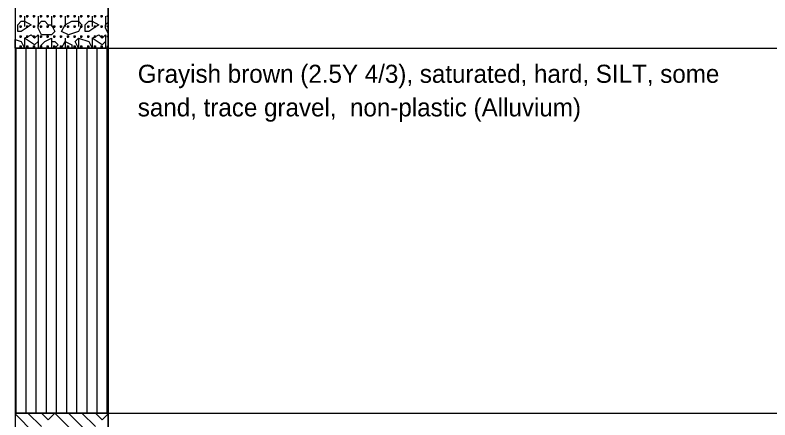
# Model space of a CAD drawing. Extents: x 9419 to 9552, y 6780 to 6865.
# Drawn here: x 9438.31 to 9447.62, y 6822.43 to 6827.42 of the extents above; entities that cross this region are included whole.
import ezdxf

# ---------------------------------------------------------------- set-up
doc = ezdxf.new("R2010")
doc.units = 0
doc.layers.add('7', color=7, linetype='Continuous')
doc.layers.add('8', color=7, linetype='Continuous')

msp = doc.modelspace()

# ---------------------------------------------------------------- linework, layer by layer
at = {"layer": '7'}
for p, q in [((9438.3144, 6832.0106), (9438.3144, 6827.0106)), ((9438.3144, 6832.0106), (9438.3144, 6827.0106)), ((9438.3144, 6832.0106), (9438.3144, 6827.0106)), ((9439.4627, 6827.0106), (9439.4627, 6832.0106)), ((9439.4627, 6827.0106), (9439.4627, 6832.0106)), ((9439.4627, 6827.0106), (9439.4627, 6832.0106)), ((9438.3144, 6827.0106), (9439.4627, 6827.0106)), ((9438.3144, 6827.0106), (9439.4627, 6827.0106)), ((9438.3144, 6827.0106), (9439.4627, 6827.0106)), ((9438.3144, 6827.0106), (9438.3144, 6822.5106)), ((9439.4627, 6827.0106), (9438.3144, 6827.0106)), ((9439.4627, 6822.5106), (9439.4627, 6827.0106)), ((9439.4627, 6827.0106), (9450.4053, 6827.0106)), ((9438.3144, 6822.5106), (9439.4627, 6822.5106)), ((9438.3144, 6822.5106), (9438.3144, 6822.0107)), ((9439.4627, 6822.5106), (9438.3144, 6822.5106)), ((9439.4627, 6822.0107), (9439.4627, 6822.5106)), ((9439.4627, 6822.5106), (9450.4053, 6822.5106))]:
    msp.add_line(p, q, dxfattribs=at)
for points in [[(9438.3144, 6850.5283), (9438.3144, 6821.9829)], [(9439.4627, 6850.5283), (9439.4627, 6821.9829)]]:
    msp.add_lwpolyline(points, dxfattribs=at)
at = {"layer": '8'}
for p, q in [((9438.4303, 6827.4065), (9438.4303, 6827.2815)), ((9438.5969, 6827.4065), (9438.5969, 6827.2815)), ((9438.7636, 6827.4065), (9438.7636, 6827.2815)), ((9438.9303, 6827.4065), (9438.9303, 6827.2815)), ((9439.0969, 6827.4065), (9439.0969, 6827.2815)), ((9439.2636, 6827.4065), (9439.2636, 6827.2815)), ((9439.4303, 6827.4065), (9439.4303, 6827.2815)), ((9438.4303, 6827.1356), (9438.4303, 6827.0106)), ((9438.5969, 6827.1356), (9438.5969, 6827.0106)), ((9438.7636, 6827.1356), (9438.7636, 6827.0106)), ((9438.9303, 6827.1356), (9438.9303, 6827.0106)), ((9439.0969, 6827.1356), (9439.0969, 6827.0106)), ((9439.2636, 6827.1356), (9439.2636, 6827.0106)), ((9439.4303, 6827.1356), (9439.4303, 6827.0106)), ((9438.3261, 6826.7606), (9438.3261, 6827.0106)), ((9438.4511, 6826.7606), (9438.4511, 6827.0106)), ((9438.5761, 6826.7606), (9438.5761, 6827.0106)), ((9438.7011, 6826.7606), (9438.7011, 6827.0106)), ((9438.8261, 6826.7606), (9438.8261, 6827.0106)), ((9438.9511, 6826.7606), (9438.9511, 6827.0106)), ((9439.0761, 6826.7606), (9439.0761, 6827.0106)), ((9439.2011, 6826.7606), (9439.2011, 6827.0106)), ((9439.3261, 6826.7606), (9439.3261, 6827.0106)), ((9439.4511, 6826.7606), (9439.4511, 6827.0106)), ((9438.3261, 6826.5106), (9438.3261, 6826.7606)), ((9438.4511, 6826.5106), (9438.4511, 6826.7606)), ((9438.5761, 6826.5106), (9438.5761, 6826.7606)), ((9438.7011, 6826.5106), (9438.7011, 6826.7606)), ((9438.8261, 6826.5106), (9438.8261, 6826.7606)), ((9438.9511, 6826.5106), (9438.9511, 6826.7606)), ((9439.0761, 6826.5106), (9439.0761, 6826.7606)), ((9439.2011, 6826.5106), (9439.2011, 6826.7606)), ((9439.3261, 6826.5106), (9439.3261, 6826.7606)), ((9439.4511, 6826.5106), (9439.4511, 6826.7606)), ((9438.3261, 6826.2606), (9438.3261, 6826.5106)), ((9438.4511, 6826.2606), (9438.4511, 6826.5106)), ((9438.5761, 6826.2606), (9438.5761, 6826.5106)), ((9438.7011, 6826.2606), (9438.7011, 6826.5106)), ((9438.8261, 6826.2606), (9438.8261, 6826.5106)), ((9438.9511, 6826.2606), (9438.9511, 6826.5106)), ((9439.0761, 6826.2606), (9439.0761, 6826.5106)), ((9439.2011, 6826.2606), (9439.2011, 6826.5106)), ((9439.3261, 6826.2606), (9439.3261, 6826.5106)), ((9439.4511, 6826.2606), (9439.4511, 6826.5106)), ((9438.3261, 6826.0106), (9438.3261, 6826.2606)), ((9438.4511, 6826.0106), (9438.4511, 6826.2606)), ((9438.5761, 6826.0106), (9438.5761, 6826.2606)), ((9438.7011, 6826.0106), (9438.7011, 6826.2606)), ((9438.8261, 6826.0106), (9438.8261, 6826.2606)), ((9438.9511, 6826.0106), (9438.9511, 6826.2606)), ((9439.0761, 6826.0106), (9439.0761, 6826.2606)), ((9439.2011, 6826.0106), (9439.2011, 6826.2606)), ((9439.3261, 6826.0106), (9439.3261, 6826.2606)), ((9439.4511, 6826.0106), (9439.4511, 6826.2606)), ((9438.3261, 6825.7606), (9438.3261, 6826.0106)), ((9438.4511, 6825.7606), (9438.4511, 6826.0106)), ((9438.5761, 6825.7606), (9438.5761, 6826.0106)), ((9438.7011, 6825.7606), (9438.7011, 6826.0106)), ((9438.8261, 6825.7606), (9438.8261, 6826.0106)), ((9438.9511, 6825.7606), (9438.9511, 6826.0106)), ((9439.0761, 6825.7606), (9439.0761, 6826.0106)), ((9439.2011, 6825.7606), (9439.2011, 6826.0106)), ((9439.3261, 6825.7606), (9439.3261, 6826.0106)), ((9439.4511, 6825.7606), (9439.4511, 6826.0106)), ((9438.3261, 6825.5106), (9438.3261, 6825.7606)), ((9438.4511, 6825.5106), (9438.4511, 6825.7606)), ((9438.5761, 6825.5106), (9438.5761, 6825.7606)), ((9438.7011, 6825.5106), (9438.7011, 6825.7606)), ((9438.8261, 6825.5106), (9438.8261, 6825.7606)), ((9438.9511, 6825.5106), (9438.9511, 6825.7606)), ((9439.0761, 6825.5106), (9439.0761, 6825.7606)), ((9439.2011, 6825.5106), (9439.2011, 6825.7606)), ((9439.3261, 6825.5106), (9439.3261, 6825.7606)), ((9439.4511, 6825.5106), (9439.4511, 6825.7606)), ((9438.3261, 6825.2606), (9438.3261, 6825.5106)), ((9438.4511, 6825.2606), (9438.4511, 6825.5106)), ((9438.5761, 6825.2606), (9438.5761, 6825.5106)), ((9438.7011, 6825.2606), (9438.7011, 6825.5106)), ((9438.8261, 6825.2606), (9438.8261, 6825.5106)), ((9438.9511, 6825.2606), (9438.9511, 6825.5106)), ((9439.0761, 6825.2606), (9439.0761, 6825.5106)), ((9439.2011, 6825.2606), (9439.2011, 6825.5106)), ((9439.3261, 6825.2606), (9439.3261, 6825.5106)), ((9439.4511, 6825.2606), (9439.4511, 6825.5106)), ((9438.3261, 6825.0106), (9438.3261, 6825.2606)), ((9438.4511, 6825.0106), (9438.4511, 6825.2606)), ((9438.5761, 6825.0106), (9438.5761, 6825.2606)), ((9438.7011, 6825.0106), (9438.7011, 6825.2606)), ((9438.8261, 6825.0106), (9438.8261, 6825.2606)), ((9438.9511, 6825.0106), (9438.9511, 6825.2606)), ((9439.0761, 6825.0106), (9439.0761, 6825.2606)), ((9439.2011, 6825.0106), (9439.2011, 6825.2606)), ((9439.3261, 6825.0106), (9439.3261, 6825.2606)), ((9439.4511, 6825.0106), (9439.4511, 6825.2606)), ((9438.3261, 6824.7606), (9438.3261, 6825.0106)), ((9438.4511, 6824.7606), (9438.4511, 6825.0106)), ((9438.5761, 6824.7606), (9438.5761, 6825.0106)), ((9438.7011, 6824.7606), (9438.7011, 6825.0106)), ((9438.8261, 6824.7606), (9438.8261, 6825.0106)), ((9438.9511, 6824.7606), (9438.9511, 6825.0106)), ((9439.0761, 6824.7606), (9439.0761, 6825.0106)), ((9439.2011, 6824.7606), (9439.2011, 6825.0106)), ((9439.3261, 6824.7606), (9439.3261, 6825.0106)), ((9439.4511, 6824.7606), (9439.4511, 6825.0106)), ((9438.3261, 6824.5106), (9438.3261, 6824.7606)), ((9438.4511, 6824.5106), (9438.4511, 6824.7606)), ((9438.5761, 6824.5106), (9438.5761, 6824.7606)), ((9438.7011, 6824.5106), (9438.7011, 6824.7606)), ((9438.8261, 6824.5106), (9438.8261, 6824.7606)), ((9438.9511, 6824.5106), (9438.9511, 6824.7606)), ((9439.0761, 6824.5106), (9439.0761, 6824.7606)), ((9439.2011, 6824.5106), (9439.2011, 6824.7606)), ((9439.3261, 6824.5106), (9439.3261, 6824.7606)), ((9439.4511, 6824.5106), (9439.4511, 6824.7606)), ((9438.3261, 6824.2606), (9438.3261, 6824.5106)), ((9438.4511, 6824.2606), (9438.4511, 6824.5106)), ((9438.5761, 6824.2606), (9438.5761, 6824.5106)), ((9438.7011, 6824.2606), (9438.7011, 6824.5106)), ((9438.8261, 6824.2606), (9438.8261, 6824.5106)), ((9438.9511, 6824.2606), (9438.9511, 6824.5106)), ((9439.0761, 6824.2606), (9439.0761, 6824.5106)), ((9439.2011, 6824.2606), (9439.2011, 6824.5106)), ((9439.3261, 6824.2606), (9439.3261, 6824.5106)), ((9439.4511, 6824.2606), (9439.4511, 6824.5106)), ((9438.3261, 6824.0106), (9438.3261, 6824.2606)), ((9438.4511, 6824.0106), (9438.4511, 6824.2606)), ((9438.5761, 6824.0106), (9438.5761, 6824.2606)), ((9438.7011, 6824.0106), (9438.7011, 6824.2606)), ((9438.8261, 6824.0106), (9438.8261, 6824.2606)), ((9438.9511, 6824.0106), (9438.9511, 6824.2606)), ((9439.0761, 6824.0106), (9439.0761, 6824.2606)), ((9439.2011, 6824.0106), (9439.2011, 6824.2606)), ((9439.3261, 6824.0106), (9439.3261, 6824.2606)), ((9439.4511, 6824.0106), (9439.4511, 6824.2606)), ((9438.3261, 6823.7606), (9438.3261, 6824.0106)), ((9438.4511, 6823.7606), (9438.4511, 6824.0106)), ((9438.5761, 6823.7606), (9438.5761, 6824.0106)), ((9438.7011, 6823.7606), (9438.7011, 6824.0106)), ((9438.8261, 6823.7606), (9438.8261, 6824.0106)), ((9438.9511, 6823.7606), (9438.9511, 6824.0106)), ((9439.0761, 6823.7606), (9439.0761, 6824.0106)), ((9439.2011, 6823.7606), (9439.2011, 6824.0106)), ((9439.3261, 6823.7606), (9439.3261, 6824.0106)), ((9439.4511, 6823.7606), (9439.4511, 6824.0106)), ((9438.3261, 6823.5106), (9438.3261, 6823.7606)), ((9438.4511, 6823.5106), (9438.4511, 6823.7606)), ((9438.5761, 6823.5106), (9438.5761, 6823.7606)), ((9438.7011, 6823.5106), (9438.7011, 6823.7606)), ((9438.8261, 6823.5106), (9438.8261, 6823.7606)), ((9438.9511, 6823.5106), (9438.9511, 6823.7606)), ((9439.0761, 6823.5106), (9439.0761, 6823.7606)), ((9439.2011, 6823.5106), (9439.2011, 6823.7606)), ((9439.3261, 6823.5106), (9439.3261, 6823.7606)), ((9439.4511, 6823.5106), (9439.4511, 6823.7606)), ((9438.3261, 6823.2606), (9438.3261, 6823.5106)), ((9438.4511, 6823.2606), (9438.4511, 6823.5106)), ((9438.5761, 6823.2606), (9438.5761, 6823.5106)), ((9438.7011, 6823.2606), (9438.7011, 6823.5106)), ((9438.8261, 6823.2606), (9438.8261, 6823.5106)), ((9438.9511, 6823.2606), (9438.9511, 6823.5106)), ((9439.0761, 6823.2606), (9439.0761, 6823.5106)), ((9439.2011, 6823.2606), (9439.2011, 6823.5106)), ((9439.3261, 6823.2606), (9439.3261, 6823.5106)), ((9439.4511, 6823.2606), (9439.4511, 6823.5106)), ((9438.3261, 6823.0106), (9438.3261, 6823.2606)), ((9438.4511, 6823.0106), (9438.4511, 6823.2606)), ((9438.5761, 6823.0106), (9438.5761, 6823.2606)), ((9438.7011, 6823.0106), (9438.7011, 6823.2606)), ((9438.8261, 6823.0106), (9438.8261, 6823.2606)), ((9438.9511, 6823.0106), (9438.9511, 6823.2606)), ((9439.0761, 6823.0106), (9439.0761, 6823.2606)), ((9439.2011, 6823.0106), (9439.2011, 6823.2606)), ((9439.3261, 6823.0106), (9439.3261, 6823.2606)), ((9439.4511, 6823.0106), (9439.4511, 6823.2606)), ((9438.3261, 6822.7607), (9438.3261, 6823.0106)), ((9438.4511, 6822.7607), (9438.4511, 6823.0106)), ((9438.5761, 6822.7607), (9438.5761, 6823.0106)), ((9438.7011, 6822.7607), (9438.7011, 6823.0106)), ((9438.8261, 6822.7607), (9438.8261, 6823.0106)), ((9438.9511, 6822.7607), (9438.9511, 6823.0106)), ((9439.0761, 6822.7607), (9439.0761, 6823.0106)), ((9439.2011, 6822.7607), (9439.2011, 6823.0106)), ((9439.3261, 6822.7607), (9439.3261, 6823.0106)), ((9439.4511, 6822.7607), (9439.4511, 6823.0106)), ((9438.3261, 6822.5106), (9438.3261, 6822.7607)), ((9438.4511, 6822.5106), (9438.4511, 6822.7607)), ((9438.5761, 6822.5106), (9438.5761, 6822.7607)), ((9438.7011, 6822.5106), (9438.7011, 6822.7607)), ((9438.8261, 6822.5106), (9438.8261, 6822.7607)), ((9438.9511, 6822.5106), (9438.9511, 6822.7607)), ((9439.0761, 6822.5106), (9439.0761, 6822.7607)), ((9439.2011, 6822.5106), (9439.2011, 6822.7607)), ((9439.3261, 6822.5106), (9439.3261, 6822.7607)), ((9439.4511, 6822.5106), (9439.4511, 6822.7607)), ((9438.3144, 6822.5015), (9438.5553, 6822.2607)), ((9438.4719, 6822.5106), (9438.6386, 6822.344)), ((9438.6386, 6822.5106), (9438.7219, 6822.4273)), ((9438.8053, 6822.5106), (9438.7219, 6822.4273)), ((9438.8053, 6822.5107), (9439.1386, 6822.1773)), ((9438.9719, 6822.5106), (9439.2219, 6822.2607)), ((9439.1386, 6822.5106), (9439.3053, 6822.344)), ((9439.3053, 6822.5106), (9439.3886, 6822.4273)), ((9439.4627, 6822.5015), (9439.3886, 6822.4273))]:
    msp.add_line(p, q, dxfattribs=at)
for points in [[(9438.3719, 6827.3971), (9438.3886, 6827.3971), (9438.3719, 6827.4138)], [(9438.3886, 6827.4138), (9438.3886, 6827.3971), (9438.3719, 6827.4138), (9438.3886, 6827.4138)], [(9438.4553, 6827.3971), (9438.4719, 6827.3971), (9438.4553, 6827.4138)], [(9438.4719, 6827.4138), (9438.4719, 6827.3971), (9438.4553, 6827.4138), (9438.4719, 6827.4138)], [(9438.5386, 6827.3971), (9438.5553, 6827.3971), (9438.5386, 6827.4138)], [(9438.5553, 6827.4138), (9438.5553, 6827.3971), (9438.5386, 6827.4138), (9438.5553, 6827.4138)], [(9438.6219, 6827.3971), (9438.6386, 6827.3971), (9438.6219, 6827.4138)], [(9438.6386, 6827.4138), (9438.6386, 6827.3971), (9438.6219, 6827.4138), (9438.6386, 6827.4138)], [(9438.7053, 6827.3971), (9438.7219, 6827.3971), (9438.7053, 6827.4138)], [(9438.7219, 6827.4138), (9438.7219, 6827.3971), (9438.7053, 6827.4138), (9438.7219, 6827.4138)], [(9438.7886, 6827.3971), (9438.8053, 6827.3971), (9438.7886, 6827.4138)], [(9438.8053, 6827.4138), (9438.8053, 6827.3971), (9438.7886, 6827.4138), (9438.8053, 6827.4138)], [(9438.8719, 6827.3971), (9438.8886, 6827.3971), (9438.8719, 6827.4138)], [(9438.8886, 6827.4138), (9438.8886, 6827.3971), (9438.8719, 6827.4138), (9438.8886, 6827.4138)], [(9438.9553, 6827.3971), (9438.9719, 6827.3971), (9438.9553, 6827.4138)], [(9438.9719, 6827.4138), (9438.9719, 6827.3971), (9438.9553, 6827.4138), (9438.9719, 6827.4138)], [(9439.0386, 6827.3971), (9439.0553, 6827.3971), (9439.0386, 6827.4138)], [(9439.0553, 6827.4138), (9439.0553, 6827.3971), (9439.0386, 6827.4138), (9439.0553, 6827.4138)], [(9439.1219, 6827.3971), (9439.1386, 6827.3971), (9439.1219, 6827.4138)], [(9439.1386, 6827.4138), (9439.1386, 6827.3971), (9439.1219, 6827.4138), (9439.1386, 6827.4138)], [(9439.2053, 6827.3971), (9439.2219, 6827.3971), (9439.2053, 6827.4138)], [(9439.2219, 6827.4138), (9439.2219, 6827.3971), (9439.2053, 6827.4138), (9439.2219, 6827.4138)], [(9439.2886, 6827.3971), (9439.3053, 6827.3971), (9439.2886, 6827.4138)], [(9439.3053, 6827.4138), (9439.3053, 6827.3971), (9439.2886, 6827.4138), (9439.3053, 6827.4138)], [(9439.3719, 6827.3971), (9439.3886, 6827.3971), (9439.3719, 6827.4138)], [(9439.3886, 6827.4138), (9439.3886, 6827.3971), (9439.3719, 6827.4138), (9439.3886, 6827.4138)], [(9439.4627, 6827.3971), (9439.4553, 6827.3971), (9439.4553, 6827.4138), (9439.4627, 6827.4138)], [(9438.3886, 6827.219), (9438.3469, 6827.219), (9438.3469, 6827.3023), (9438.3886, 6827.344), (9438.4303, 6827.344), (9438.5136, 6827.3023)], [(9438.6386, 6827.1773), (9438.5969, 6827.2606), (9438.5969, 6827.3023), (9438.6386, 6827.344), (9438.6803, 6827.344), (9438.7219, 6827.3023), (9438.7636, 6827.3023), (9438.8053, 6827.219), (9438.7636, 6827.1773)], [(9439.0136, 6827.344), (9439.0969, 6827.344), (9439.1386, 6827.3023), (9439.0969, 6827.219), (9438.9719, 6827.1773), (9438.8886, 6827.219), (9438.9303, 6827.3023)], [(9439.2219, 6827.219), (9439.1803, 6827.219), (9439.1803, 6827.3023), (9439.2219, 6827.344), (9439.2636, 6827.344), (9439.3469, 6827.3023)], [(9439.4627, 6827.1957), (9439.4303, 6827.2606), (9439.4303, 6827.3023), (9439.4627, 6827.3348)], [(9438.3719, 6827.2733), (9438.3886, 6827.2733), (9438.3719, 6827.29)], [(9438.3886, 6827.29), (9438.3886, 6827.2733), (9438.3719, 6827.29), (9438.3886, 6827.29)], [(9438.4553, 6827.2733), (9438.4719, 6827.2733), (9438.4553, 6827.29)], [(9438.4719, 6827.29), (9438.4719, 6827.2733), (9438.4553, 6827.29), (9438.4719, 6827.29)], [(9438.5386, 6827.2733), (9438.5553, 6827.2733), (9438.5386, 6827.29)], [(9438.5553, 6827.29), (9438.5553, 6827.2733), (9438.5386, 6827.29), (9438.5553, 6827.29)], [(9438.6219, 6827.2733), (9438.6386, 6827.2733), (9438.6219, 6827.29)], [(9438.6386, 6827.29), (9438.6386, 6827.2733), (9438.6219, 6827.29), (9438.6386, 6827.29)], [(9438.7053, 6827.2733), (9438.7219, 6827.2733), (9438.7053, 6827.29)], [(9438.7219, 6827.29), (9438.7219, 6827.2733), (9438.7053, 6827.29), (9438.7219, 6827.29)], [(9438.7886, 6827.2733), (9438.8053, 6827.2733), (9438.7886, 6827.29)], [(9438.8053, 6827.29), (9438.8053, 6827.2733), (9438.7886, 6827.29), (9438.8053, 6827.29)], [(9438.8719, 6827.2733), (9438.8886, 6827.2733), (9438.8719, 6827.29)], [(9438.8886, 6827.29), (9438.8886, 6827.2733), (9438.8719, 6827.29), (9438.8886, 6827.29)], [(9438.9553, 6827.2733), (9438.9719, 6827.2733), (9438.9553, 6827.29)], [(9438.9719, 6827.29), (9438.9719, 6827.2733), (9438.9553, 6827.29), (9438.9719, 6827.29)], [(9439.0386, 6827.2733), (9439.0553, 6827.2733), (9439.0386, 6827.29)], [(9439.0553, 6827.29), (9439.0553, 6827.2733), (9439.0386, 6827.29), (9439.0553, 6827.29)], [(9439.1219, 6827.2733), (9439.1386, 6827.2733), (9439.1219, 6827.29)], [(9439.1386, 6827.29), (9439.1386, 6827.2733), (9439.1219, 6827.29), (9439.1386, 6827.29)], [(9439.2053, 6827.2733), (9439.2219, 6827.2733), (9439.2053, 6827.29)], [(9439.2219, 6827.29), (9439.2219, 6827.2733), (9439.2053, 6827.29), (9439.2219, 6827.29)], [(9439.2886, 6827.2733), (9439.3053, 6827.2733), (9439.2886, 6827.29)], [(9439.3053, 6827.29), (9439.3053, 6827.2733), (9439.2886, 6827.29), (9439.3053, 6827.29)], [(9439.3719, 6827.2733), (9439.3886, 6827.2733), (9439.3719, 6827.29)], [(9439.3886, 6827.29), (9439.3886, 6827.2733), (9439.3719, 6827.29), (9439.3886, 6827.29)], [(9439.4627, 6827.2733), (9439.4553, 6827.2733), (9439.4553, 6827.29), (9439.4627, 6827.29)], [(9438.3144, 6827.0106), (9438.3144, 6827.1187), (9438.3886, 6827.094), (9438.4303, 6827.0106), (9438.4303, 6827.0106)], [(9438.3719, 6827.1495), (9438.3886, 6827.1495), (9438.3719, 6827.1661)], [(9438.3886, 6827.1661), (9438.3886, 6827.1495), (9438.3719, 6827.1661), (9438.3886, 6827.1661)], [(9438.4303, 6827.1356), (9438.5136, 6827.1773), (9438.5553, 6827.1356), (9438.5969, 6827.1773), (9438.5969, 6827.094), (9438.5553, 6827.0523)], [(9438.4553, 6827.1495), (9438.4719, 6827.1495), (9438.4553, 6827.1661)], [(9438.4719, 6827.1661), (9438.4719, 6827.1495), (9438.4553, 6827.1661), (9438.4719, 6827.1661)], [(9438.5386, 6827.1495), (9438.5553, 6827.1495), (9438.5386, 6827.1661)], [(9438.5553, 6827.1661), (9438.5553, 6827.1495), (9438.5386, 6827.1661), (9438.5553, 6827.1661)], [(9438.6219, 6827.1495), (9438.6386, 6827.1495), (9438.6219, 6827.1661)], [(9438.6386, 6827.1661), (9438.6386, 6827.1495), (9438.6219, 6827.1661), (9438.6386, 6827.1661)], [(9438.6386, 6827.0106), (9438.6386, 6827.0106), (9438.6386, 6827.0523), (9438.6803, 6827.094), (9438.7636, 6827.1356), (9438.7636, 6827.094), (9438.8053, 6827.094), (9438.8469, 6827.0523), (9438.8053, 6827.0106), (9438.8053, 6827.0106)], [(9438.7053, 6827.1495), (9438.7219, 6827.1495), (9438.7053, 6827.1661)], [(9438.7219, 6827.1661), (9438.7219, 6827.1495), (9438.7053, 6827.1661), (9438.7219, 6827.1661)], [(9438.7886, 6827.1495), (9438.8053, 6827.1495), (9438.7886, 6827.1661)], [(9438.8053, 6827.1661), (9438.8053, 6827.1495), (9438.7886, 6827.1661), (9438.8053, 6827.1661)], [(9438.8719, 6827.1495), (9438.8886, 6827.1495), (9438.8719, 6827.1661)], [(9438.8886, 6827.1661), (9438.8886, 6827.1495), (9438.8719, 6827.1661), (9438.8886, 6827.1661)], [(9438.9553, 6827.1495), (9438.9719, 6827.1495), (9438.9553, 6827.1661)], [(9438.9719, 6827.1661), (9438.9719, 6827.1495), (9438.9553, 6827.1661), (9438.9719, 6827.1661)], [(9439.0386, 6827.1495), (9439.0553, 6827.1495), (9439.0386, 6827.1661)], [(9439.0553, 6827.1661), (9439.0553, 6827.1495), (9439.0386, 6827.1661), (9439.0553, 6827.1661)], [(9439.0969, 6827.0106), (9439.0969, 6827.0106), (9439.0553, 6827.094), (9439.0969, 6827.1356), (9439.2219, 6827.094), (9439.2636, 6827.0106), (9439.2636, 6827.0106)], [(9439.1219, 6827.1495), (9439.1386, 6827.1495), (9439.1219, 6827.1661)], [(9439.1386, 6827.1661), (9439.1386, 6827.1495), (9439.1219, 6827.1661), (9439.1386, 6827.1661)], [(9439.2053, 6827.1495), (9439.2219, 6827.1495), (9439.2053, 6827.1661)], [(9439.2219, 6827.1661), (9439.2219, 6827.1495), (9439.2053, 6827.1661), (9439.2219, 6827.1661)], [(9439.2636, 6827.1356), (9439.3469, 6827.1773), (9439.3886, 6827.1356), (9439.4303, 6827.1773), (9439.4303, 6827.094), (9439.3886, 6827.0523)], [(9439.2886, 6827.1495), (9439.3053, 6827.1495), (9439.2886, 6827.1661)], [(9439.3053, 6827.1661), (9439.3053, 6827.1495), (9439.2886, 6827.1661), (9439.3053, 6827.1661)], [(9439.3719, 6827.1495), (9439.3886, 6827.1495), (9439.3719, 6827.1661)], [(9439.3886, 6827.1661), (9439.3886, 6827.1495), (9439.3719, 6827.1661), (9439.3886, 6827.1661)], [(9439.4627, 6827.1495), (9439.4553, 6827.1495), (9439.4553, 6827.1661), (9439.4627, 6827.1661)], [(9438.3719, 6827.0256), (9438.3886, 6827.0256), (9438.3719, 6827.0423)], [(9438.3886, 6827.0423), (9438.3886, 6827.0256), (9438.3719, 6827.0423), (9438.3886, 6827.0423)], [(9438.4553, 6827.0256), (9438.4719, 6827.0256), (9438.4553, 6827.0423)], [(9438.4719, 6827.0423), (9438.4719, 6827.0256), (9438.4553, 6827.0423), (9438.4719, 6827.0423)], [(9438.5386, 6827.0256), (9438.5553, 6827.0256), (9438.5386, 6827.0423)], [(9438.5553, 6827.0423), (9438.5553, 6827.0256), (9438.5386, 6827.0423), (9438.5553, 6827.0423)], [(9438.6219, 6827.0256), (9438.6386, 6827.0256), (9438.6219, 6827.0423)], [(9438.6386, 6827.0423), (9438.6386, 6827.0256), (9438.6219, 6827.0423), (9438.6386, 6827.0423)], [(9438.7053, 6827.0256), (9438.7219, 6827.0256), (9438.7053, 6827.0423)], [(9438.7219, 6827.0423), (9438.7219, 6827.0256), (9438.7053, 6827.0423), (9438.7219, 6827.0423)], [(9438.7886, 6827.0256), (9438.8053, 6827.0256), (9438.7886, 6827.0423)], [(9438.8053, 6827.0423), (9438.8053, 6827.0256), (9438.7886, 6827.0423), (9438.8053, 6827.0423)], [(9438.8719, 6827.0256), (9438.8886, 6827.0256), (9438.8719, 6827.0423)], [(9438.8886, 6827.0423), (9438.8886, 6827.0256), (9438.8719, 6827.0423), (9438.8886, 6827.0423)], [(9438.8886, 6827.0106), (9438.8886, 6827.0106), (9438.9303, 6827.094), (9439.0136, 6827.0523), (9439.0136, 6827.0106)], [(9438.9553, 6827.0256), (9438.9719, 6827.0256), (9438.9553, 6827.0423)], [(9438.9719, 6827.0423), (9438.9719, 6827.0256), (9438.9553, 6827.0423), (9438.9719, 6827.0423)], [(9439.0386, 6827.0256), (9439.0553, 6827.0256), (9439.0386, 6827.0423)], [(9439.0553, 6827.0423), (9439.0553, 6827.0256), (9439.0386, 6827.0423), (9439.0553, 6827.0423)], [(9439.1219, 6827.0256), (9439.1386, 6827.0256), (9439.1219, 6827.0423)], [(9439.1386, 6827.0423), (9439.1386, 6827.0256), (9439.1219, 6827.0423), (9439.1386, 6827.0423)], [(9439.2053, 6827.0256), (9439.2219, 6827.0256), (9439.2053, 6827.0423)], [(9439.2219, 6827.0423), (9439.2219, 6827.0256), (9439.2053, 6827.0423), (9439.2219, 6827.0423)], [(9439.2886, 6827.0256), (9439.3053, 6827.0256), (9439.2886, 6827.0423)], [(9439.3053, 6827.0423), (9439.3053, 6827.0256), (9439.2886, 6827.0423), (9439.3053, 6827.0423)], [(9439.3719, 6827.0256), (9439.3886, 6827.0256), (9439.3719, 6827.0423)], [(9439.3886, 6827.0423), (9439.3886, 6827.0256), (9439.3719, 6827.0423), (9439.3886, 6827.0423)], [(9439.4627, 6827.0256), (9439.4553, 6827.0256), (9439.4553, 6827.0423), (9439.4627, 6827.0423)]]:
    msp.add_lwpolyline(points, close=True, dxfattribs=at)

# ---------------------------------------------------------------- texts
at = {"layer": '7'}
for s, p in [('Grayish brown (2.5Y 4/3), saturated, hard, SILT, some', (9439.8273, 6826.5853)), ('sand, trace gravel,  non-plastic (Alluvium)', (9439.8273, 6826.1711))]:
    msp.add_text(s, height=0.2228, dxfattribs=at).set_placement(p)

doc.saveas('drawing.dxf')
